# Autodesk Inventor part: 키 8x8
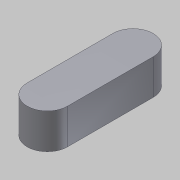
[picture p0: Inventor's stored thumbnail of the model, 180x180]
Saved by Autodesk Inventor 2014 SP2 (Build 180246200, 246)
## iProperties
Company: 한국ATC센터
Created: 2014-10
Part Number: 키 8x8
Document SubType Name: Modeling
Designer: 한국ATC센터
Density: 7.86 g/cm^3
Material: 강철, 연강
Mass: 10.2483 g
Surface Area: 7.8646 cm^2
Volume: 1.30386 cm^3
Appearance: 강철
Author: KYOUNG IL JANG
Revision Number: 1
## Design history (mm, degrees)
sketch "스케치1"
  geometry: L1 (28.264, -14)-(28.264, -31) reference; L2 (20.264, -31)-(20.264, -14) reference; A1 r 4 centre (24.264, -31) between (20.264, -31) and (28.264, -31) reference; A2 r 4 centre (24.264, -14) between (28.264, -14) and (20.264, -14) reference; 1 further point
extrude "돌출1" new body sketch "스케치1" distance "d0" = 7; taper "d1" = 0 deg
node "솔리드1"
node "참조1"
